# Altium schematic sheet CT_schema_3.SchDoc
size 380 x 341 mm
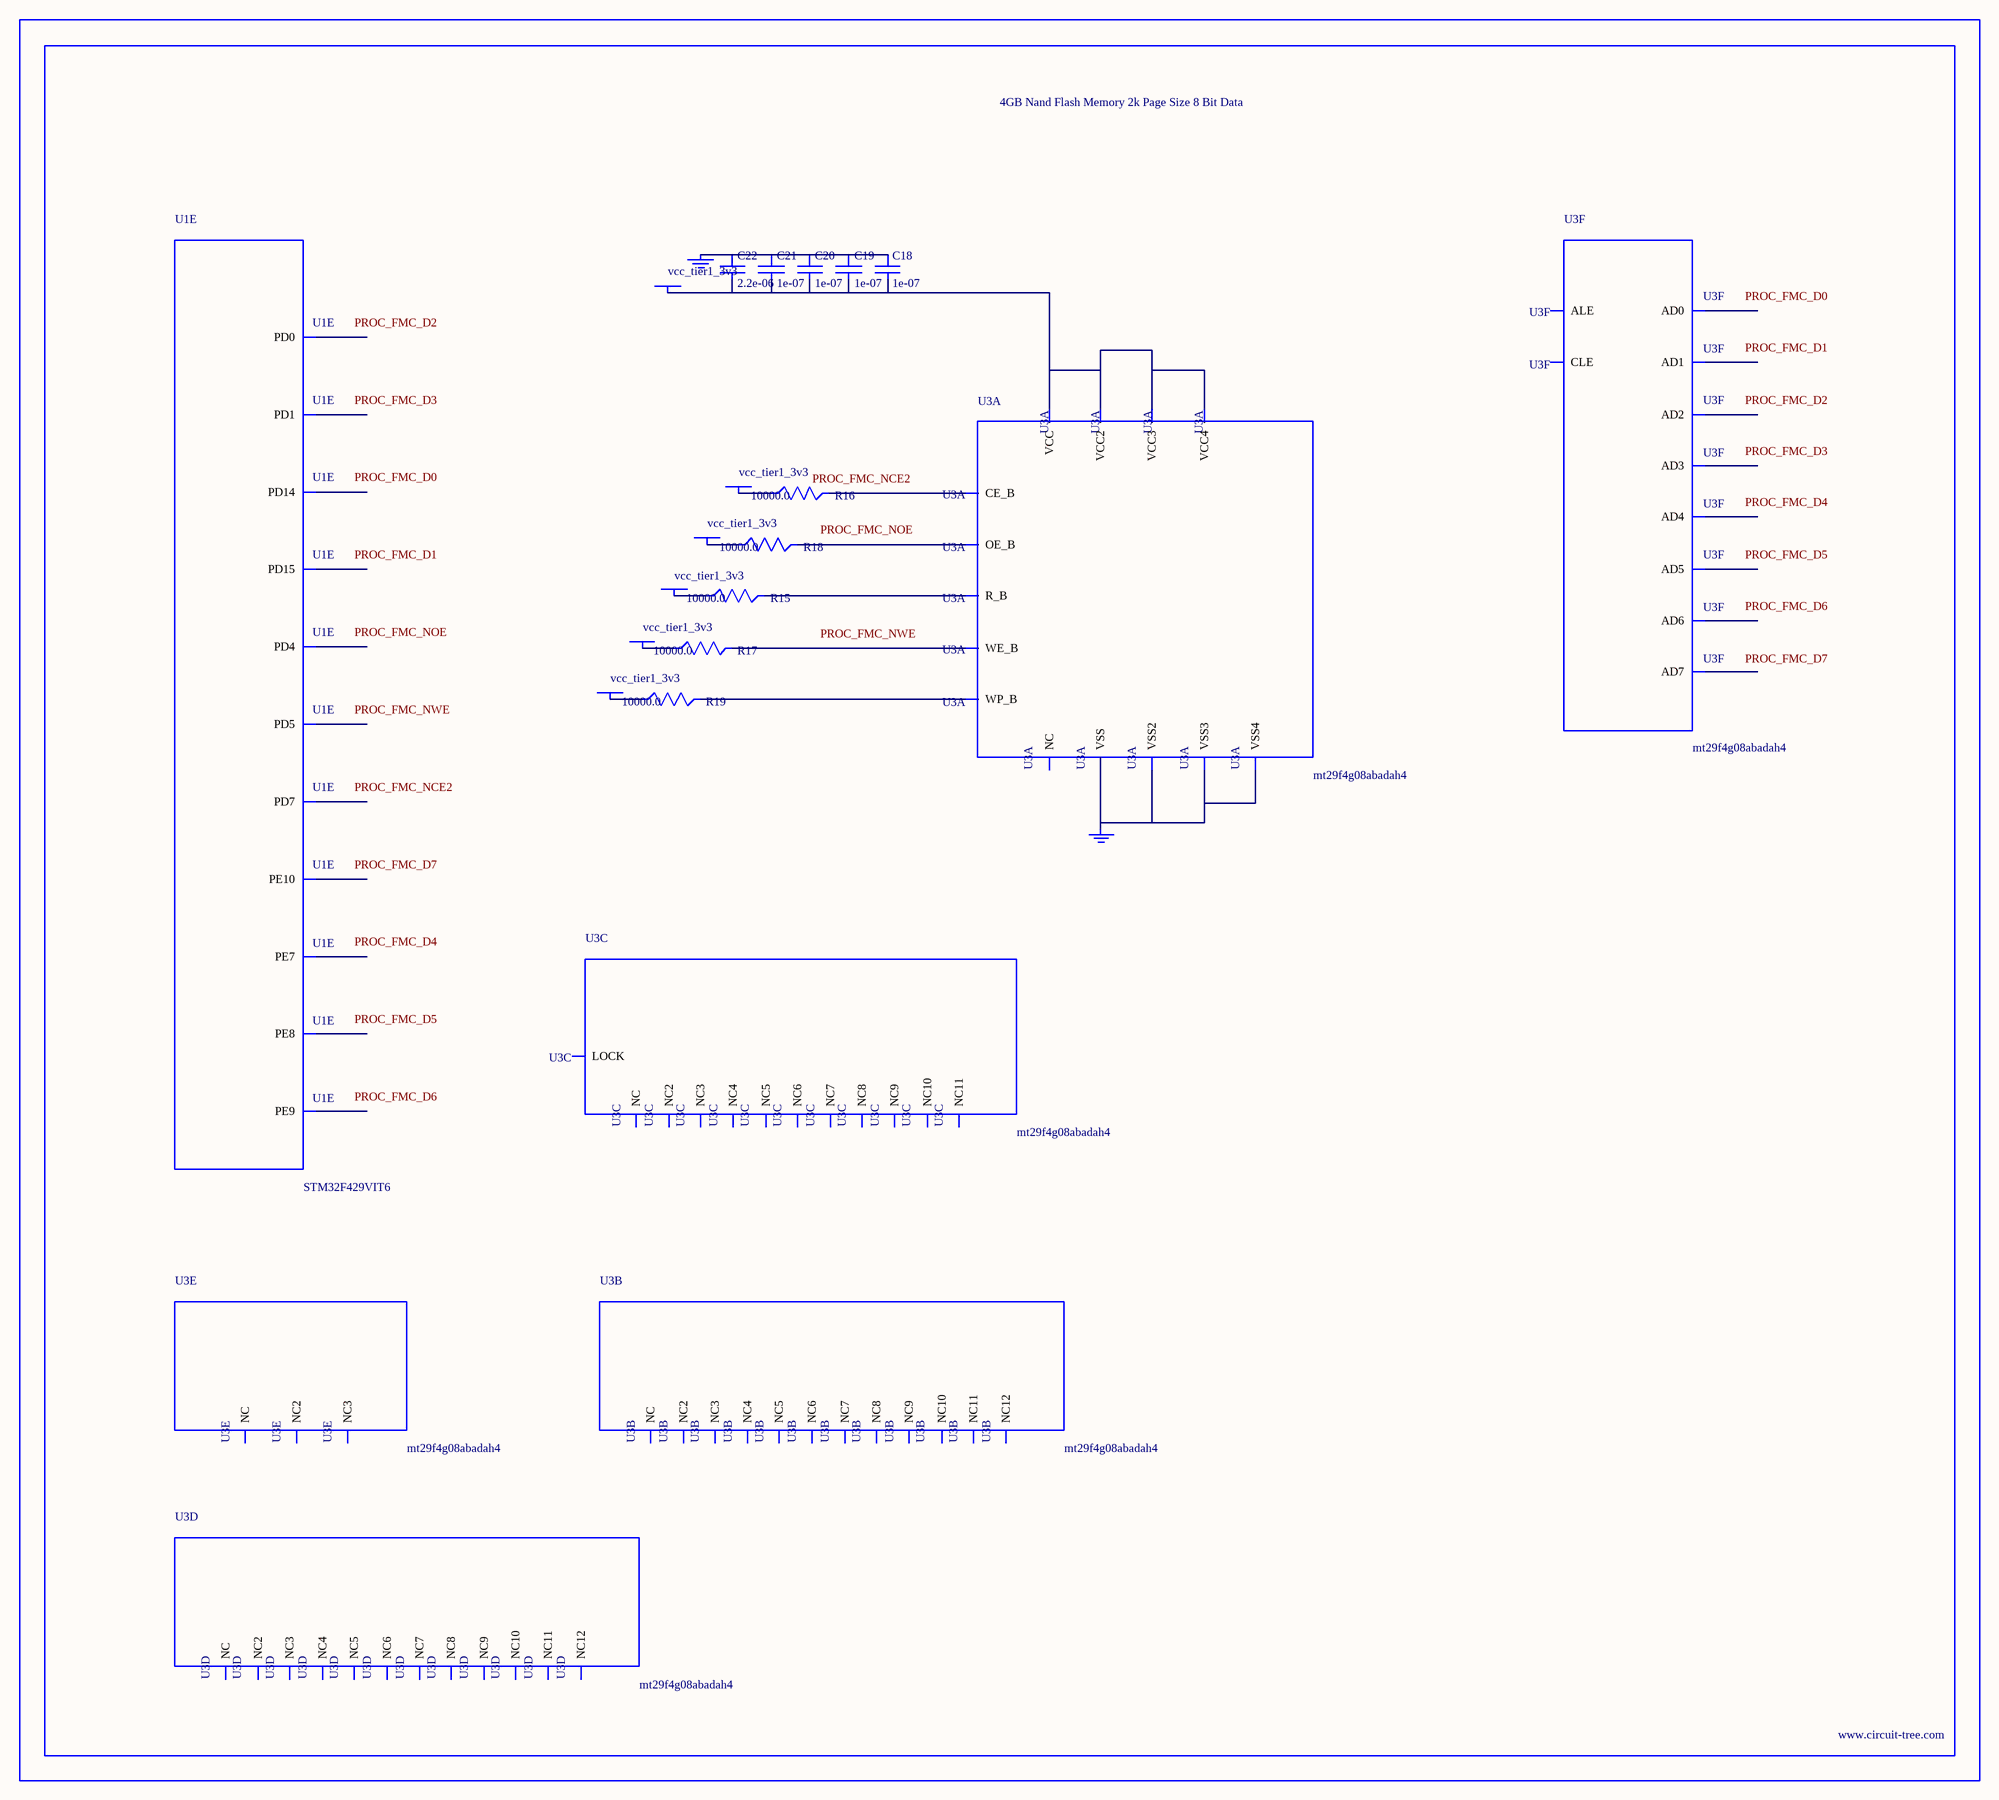
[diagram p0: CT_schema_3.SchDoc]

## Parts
BORDER2  (no value)
C18  1e-07  [C0402]
C19  1e-07  [C0402]
C20  1e-07  [C0402]
C21  1e-07  [C0402]
C22  2.2e-06  [C0603]
GND_INSTANCE_2_0  (no value)
GND_INSTANCE_2_1  (no value)
POWER_INSTANCE_2_0  vcc_tier1_3v3
POWER_INSTANCE_2_1  vcc_tier1_3v3
POWER_INSTANCE_2_2  vcc_tier1_3v3
POWER_INSTANCE_2_3  vcc_tier1_3v3
POWER_INSTANCE_2_4  vcc_tier1_3v3
POWER_INSTANCE_2_5  vcc_tier1_3v3
R15  10000.0  [R0603]
R16  10000.0  [R0603]
R17  10000.0  [R0603]
R18  10000.0  [R0603]
R19  10000.0  [R0603]
U1  STM32F429VIT6  [LQFP100]  (part E of 9)
U3  mt29f4g08abadah4  [VFBGA-63]  (parts A,B,C,D,E,F of 6)

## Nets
NetC18_1: C18.1 C19.1 C20.1 C21.1 C22.1 GND_INSTANCE_2_0.0(GND)
NetC18_2: C18.2 C19.2 C20.2 C21.2 C22.2 POWER_INSTANCE_2_0.0(PWR) U3.D3(VCC) U3.G4(VCC2) U3.H8(VCC3) U3.J6(VCC4)
NetGND_INSTANCE_2_1_0: GND_INSTANCE_2_1.0(GND) U3.C5(VSS) U3.F7(VSS2) U3.K3(VSS3) U3.K8(VSS4)
NetPOWER_INSTANCE_2_1_0: POWER_INSTANCE_2_1.0(PWR) R15.1
NetPOWER_INSTANCE_2_2_0: POWER_INSTANCE_2_2.0(PWR) R16.1
NetPOWER_INSTANCE_2_3_0: POWER_INSTANCE_2_3.0(PWR) R17.1
NetPOWER_INSTANCE_2_4_0: POWER_INSTANCE_2_4.0(PWR) R18.1
NetPOWER_INSTANCE_2_5_0: POWER_INSTANCE_2_5.0(PWR) R19.1
NetR15_2: R15.2 U3.C8(R_B)
NetR16_2: R16.2 U3.C6(CE_B)
NetR17_2: R17.2 U3.C7(WE_B)
NetR18_2: R18.2 U3.D4(OE_B)
NetR19_2: R19.2 U3.C3(WP_B)

Not connected (* = marked no-connect by the designer): U1 38(PE7) 39(PE8) 40(PE9) 41(PE10) 61(PD14) 62(PD15) 81(PD0) 82(PD1) 85(PD4) 86(PD5) 88(PD7); U3 A1(NC) A2(NC3) A9(NC4) A10(NC2) B1(NC5) B9(NC7) B10(NC6) C4(ALE) D5(CLE) D6(NC8) D7(NC9) D8(NC10) E3(NC11) E4(NC12) E5(NC) E6(NC2) E7(NC3) E8(NC4) F3(NC5) F4(NC6) F5(NC7) F6(NC8) F8(NC9) G3(NC) G5(LOCK) G6(NC10) G7(NC11) G8(NC) H3(NC2) H4(AD0) H5(NC3) H6(NC4) H7(NC5) J3(NC6) J4(AD1) J5(NC7) J7(AD5) J8(AD7) K4(AD2) K5(AD3) K6(AD4) K7(AD6) L1(NC8) L2(NC10) L9(NC11) L10(NC9) M1(NC12) M2(NC2) M9(NC3) M10(NC)

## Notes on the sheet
- Labels drawn without touching a wire or pin: PROC_FMC_D0, PROC_FMC_D1, PROC_FMC_D2, PROC_FMC_D3, PROC_FMC_D4, PROC_FMC_D5, PROC_FMC_D6, PROC_FMC_D7, PROC_FMC_NCE2, PROC_FMC_NOE, PROC_FMC_NWE

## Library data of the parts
BORDER2 = BORDER_PAGE2
C18-C21 = C0402C104K3RACTU
C22 = C0603C225K8RACTU
GND_INSTANCE_2_0 GND_INSTANCE_2_1 = GND
POWER_INSTANCE_2_0-POWER_INSTANCE_2_5 = PWR
R15-R19 = RC0603JR-0710KL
